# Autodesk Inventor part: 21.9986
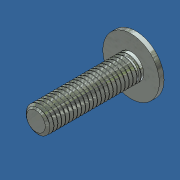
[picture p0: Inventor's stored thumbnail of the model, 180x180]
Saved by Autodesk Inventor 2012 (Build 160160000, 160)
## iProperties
Created: 2011-02
Part Number: 21.9986
Document SubType Name: Modeling
Designer: Administrator
Density: 7.85 g/cm^3
Material: Steel
Mass: 14.2875 g
Surface Area: 18.342 cm^2
Volume: 1.82006 cm^3
Description: M8X30 BUTTON HEAD FLANGE
Translation Standard: STEP AP203
FileName: 92137A654.step
PreProcessor: SolidWorks 2006233
PostProcessor: Build: 236a, Release: 2009 RTM - Date: Fri 02/22/2008
Sent Units: MM
Uncertainty: 1e-05
Author: Administrator
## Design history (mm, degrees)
feature "Base1"
body "Solid1"
